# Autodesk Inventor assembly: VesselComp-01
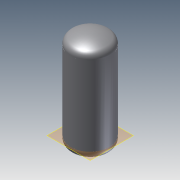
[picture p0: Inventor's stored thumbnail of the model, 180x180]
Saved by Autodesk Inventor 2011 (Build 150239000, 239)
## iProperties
Created: 2010-06
Part Number: VesselComp-01
Document SubType Name: Assembly
Designer: mklassen
OD: 24.000 in
THK: 0.500 in
LEN: 3.000 ft
Author: mklassen
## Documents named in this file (3)
- O:\cadd\tutorials\inventor 2011\iLogic\VesselComp-01.iam
- O:\cadd\tutorials\inventor 2011\iLogic\Shell-02-01.ipt
- O:\cadd\tutorials\inventor 2011\iLogic\Head-02-01.ipt
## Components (3 placed, 2 different names)
1. Shell-02:1 — Mate:2
2. Head-02:1
3. Head-02:2
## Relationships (1: Mate 1)
- Mate:2: Shell-02:1
## Named parameters: SKOFS = -152.4 mm
